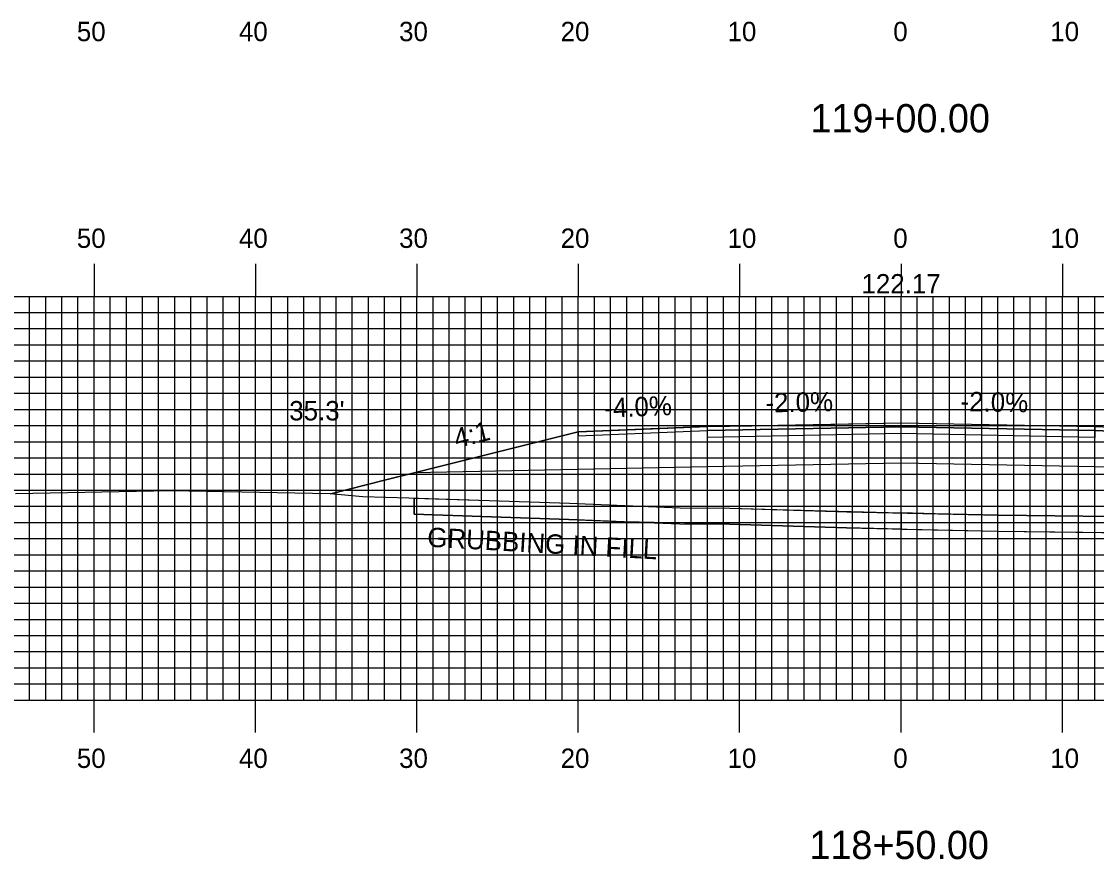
# Model space of a CAD drawing. Extents: x 1771629 to 1771972, y 442591 to 442811.
# Drawn here: x 1771740.1 to 1771806.7, y 442643.8 to 442695.7 of the extents above; entities that cross this region are included whole.
import ezdxf

# ---------------------------------------------------------------- set-up
doc = ezdxf.new("R2010")
doc.units = 0
for name, color, linetype in [('ANNOTATION', 7, 'Continuous'), ('D_Roadway_Centerline', 7, 'Continuous'), ('D_Roadway_Centerline_Text', 7, 'Continuous'), ('D_Roadway_Edge_Shoulder', 7, 'Continuous'), ('D_Roadway_Edge_TW', 7, 'Continuous'), ('D_Roadway_Pavement', 7, 'Continuous'), ('D_Roadway_SlopeLines', 7, 'Continuous'), ('D_Roadway_SubGrade', 7, 'Continuous'), ('D_Text_Standard', 7, 'Continuous'), ('GRUBBING IN FILL', 7, 'Continuous'), ('H_V ANNOTATION', 7, 'Continuous'), ('MAJOR', 7, 'Continuous'), ('MINOR', 7, 'Continuous'), ('S_Roadway_Centerline', 7, 'Continuous')]:
    doc.layers.add(name, color=color, linetype=linetype)

msp = doc.modelspace()

# ---------------------------------------------------------------- linework, layer by layer
at = {"layer": 'D_Roadway_Centerline'}
msp.add_lwpolyline([(1771759.249, 442666.447), (1771762.58, 442667.28), (1771764.404, 442667.736), (1771764.407, 442667.736), (1771764.42, 442667.74), (1771772.599, 442669.785), (1771774.581, 442670.28), (1771774.583, 442670.28), (1771778.655, 442670.443), (1771782.581, 442670.6), (1771782.585, 442670.6), (1771785.333, 442670.655), (1771794.58, 442670.84), (1771806.564, 442670.601), (1771806.581, 442670.6), (1771806.592, 442670.6), (1771814.581, 442670.28), (1771814.588, 442670.278), (1771822.681, 442668.255), (1771824.754, 442667.736), (1771824.757, 442667.736), (1771836.89, 442664.702)], dxfattribs=at)
at = {"layer": 'D_Roadway_Edge_Shoulder'}
for points in [[(1771782.581, 442670.6), (1771774.581, 442670.28), (1771774.581, 442670.03), (1771782.581, 442670.35)], [(1771806.581, 442670.6), (1771814.581, 442670.28), (1771814.581, 442670.03), (1771806.581, 442670.35)]]:
    msp.add_lwpolyline(points, close=True, dxfattribs=at)
at = {"layer": 'D_Roadway_Edge_TW'}
msp.add_lwpolyline([(1771782.581, 442670.35), (1771782.581, 442670.6), (1771794.58, 442670.84), (1771806.581, 442670.6), (1771806.581, 442670.35), (1771794.58, 442670.59)], close=True, dxfattribs=at)
at = {"layer": 'D_Roadway_Pavement'}
msp.add_lwpolyline([(1771782.581, 442669.933), (1771782.581, 442670.35), (1771794.58, 442670.59), (1771806.581, 442670.35), (1771806.581, 442669.933), (1771794.58, 442670.173)], close=True, dxfattribs=at)
at = {"layer": 'D_Roadway_SlopeLines'}
msp.add_lwpolyline([(1771774.581, 442670.28), (1771764.407, 442667.736), (1771762.58, 442667.28), (1771759.249, 442666.447)], dxfattribs=at)
at = {"layer": 'D_Roadway_SubGrade'}
msp.add_lwpolyline([(1771782.581, 442668.1), (1771764.407, 442667.736), (1771774.581, 442670.28), (1771774.581, 442670.03), (1771782.581, 442670.35), (1771794.58, 442670.59), (1771806.581, 442670.35), (1771814.581, 442670.03), (1771814.581, 442670.28), (1771824.754, 442667.736), (1771806.581, 442668.1), (1771794.58, 442668.34)], close=True, dxfattribs=at)
at = {"layer": 'GRUBBING IN FILL'}
msp.add_line((1771764.407, 442666.174), (1771764.407, 442665.173), dxfattribs=at)
msp.add_line((1771764.407, 442666.174), (1771764.407, 442665.173), dxfattribs=at)
for points in [[(1771764.407, 442666.174), (1771769.054, 442666.018), (1771774.033, 442665.85), (1771780.897, 442665.574), (1771783.979, 442665.55), (1771787.6, 442665.439), (1771794.58, 442665.253), (1771794.58, 442664.253), (1771791.195, 442664.327), (1771783.959, 442664.55), (1771777.434, 442664.713), (1771773.996, 442664.851), (1771769.201, 442665.012), (1771764.407, 442665.173)], [(1771764.407, 442666.174), (1771769.054, 442666.018), (1771774.033, 442665.85), (1771780.897, 442665.574), (1771783.979, 442665.55), (1771787.6, 442665.439), (1771794.58, 442665.253), (1771794.58, 442664.253), (1771791.195, 442664.327), (1771783.959, 442664.55), (1771777.434, 442664.713), (1771773.996, 442664.851), (1771769.201, 442665.012), (1771764.407, 442665.173)], [(1771824.754, 442664.79), (1771819.881, 442664.889), (1771815.873, 442664.937), (1771810.246, 442665.005), (1771805.849, 442665.057), (1771800.611, 442665.12), (1771796.705, 442665.206), (1771794.58, 442665.253), (1771794.58, 442664.253), (1771800.594, 442664.12), (1771810.232, 442664.005), (1771819.869, 442663.889), (1771824.754, 442663.79)], [(1771824.754, 442664.79), (1771819.881, 442664.889), (1771815.873, 442664.937), (1771810.246, 442665.005), (1771805.849, 442665.057), (1771800.611, 442665.12), (1771796.705, 442665.206), (1771794.58, 442665.253), (1771794.58, 442664.253), (1771800.594, 442664.12), (1771810.232, 442664.005), (1771819.869, 442663.889), (1771824.754, 442663.79)]]:
    msp.add_lwpolyline(points, close=True, dxfattribs=at)
msp.add_lwpolyline([(1771764.407, 442665.173), (1771773.996, 442664.851), (1771780.873, 442664.574), (1771783.959, 442664.55), (1771791.195, 442664.327), (1771800.594, 442664.12), (1771819.869, 442663.889), (1771820.358, 442663.884), (1771820.72, 442663.874), (1771824.754, 442663.79)], dxfattribs=at)
msp.add_lwpolyline([(1771764.407, 442665.173), (1771773.996, 442664.851), (1771780.873, 442664.574), (1771783.959, 442664.55), (1771791.195, 442664.327), (1771800.594, 442664.12), (1771819.869, 442663.889), (1771820.358, 442663.884), (1771820.72, 442663.874), (1771824.754, 442663.79)], dxfattribs=at)
at = {"layer": 'MAJOR'}
for p, q in [((1771744.58, 442680.669), (1771744.58, 442678.665)), ((1771754.58, 442680.669), (1771754.58, 442678.665)), ((1771764.58, 442680.669), (1771764.58, 442678.665)), ((1771774.58, 442680.669), (1771774.58, 442678.665)), ((1771784.58, 442680.669), (1771784.58, 442678.665)), ((1771794.58, 442680.669), (1771794.58, 442678.665)), ((1771804.58, 442680.669), (1771804.58, 442678.665)), ((1771654.58, 442678.665), (1771934.58, 442678.665)), ((1771654.58, 442678.665), (1771934.58, 442678.665)), ((1771744.58, 442653.665), (1771744.58, 442678.665)), ((1771754.58, 442653.665), (1771754.58, 442678.665)), ((1771764.58, 442653.665), (1771764.58, 442678.665)), ((1771774.58, 442653.665), (1771774.58, 442678.665)), ((1771784.58, 442653.665), (1771784.58, 442678.665)), ((1771794.58, 442653.665), (1771794.58, 442678.665)), ((1771804.58, 442653.665), (1771804.58, 442678.665)), ((1771654.58, 442673.665), (1771934.58, 442673.665)), ((1771654.58, 442668.665), (1771934.58, 442668.665)), ((1771654.58, 442663.665), (1771934.58, 442663.665)), ((1771654.58, 442658.665), (1771934.58, 442658.665)), ((1771654.58, 442653.665), (1771934.58, 442653.665)), ((1771654.58, 442653.665), (1771934.58, 442653.665)), ((1771744.58, 442651.661), (1771744.58, 442653.665)), ((1771754.58, 442651.661), (1771754.58, 442653.665)), ((1771764.58, 442651.661), (1771764.58, 442653.665)), ((1771774.58, 442651.661), (1771774.58, 442653.665)), ((1771784.58, 442651.661), (1771784.58, 442653.665)), ((1771794.58, 442651.661), (1771794.58, 442653.665)), ((1771804.58, 442651.661), (1771804.58, 442653.665))]:
    msp.add_line(p, q, dxfattribs=at)
at = {"layer": 'MINOR'}
for p, q in [((1771740.58, 442653.665), (1771740.58, 442678.665)), ((1771741.58, 442653.665), (1771741.58, 442678.665)), ((1771742.58, 442653.665), (1771742.58, 442678.665)), ((1771743.58, 442653.665), (1771743.58, 442678.665)), ((1771745.58, 442653.665), (1771745.58, 442678.665)), ((1771746.58, 442653.665), (1771746.58, 442678.665)), ((1771747.58, 442653.665), (1771747.58, 442678.665)), ((1771748.58, 442653.665), (1771748.58, 442678.665)), ((1771749.58, 442653.665), (1771749.58, 442678.665)), ((1771750.58, 442653.665), (1771750.58, 442678.665)), ((1771751.58, 442653.665), (1771751.58, 442678.665)), ((1771752.58, 442653.665), (1771752.58, 442678.665)), ((1771753.58, 442653.665), (1771753.58, 442678.665)), ((1771755.58, 442653.665), (1771755.58, 442678.665)), ((1771756.58, 442653.665), (1771756.58, 442678.665)), ((1771757.58, 442653.665), (1771757.58, 442678.665)), ((1771758.58, 442653.665), (1771758.58, 442678.665)), ((1771759.58, 442653.665), (1771759.58, 442678.665)), ((1771760.58, 442653.665), (1771760.58, 442678.665)), ((1771761.58, 442653.665), (1771761.58, 442678.665)), ((1771762.58, 442653.665), (1771762.58, 442678.665)), ((1771763.58, 442653.665), (1771763.58, 442678.665)), ((1771765.58, 442653.665), (1771765.58, 442678.665)), ((1771766.58, 442653.665), (1771766.58, 442678.665)), ((1771767.58, 442653.665), (1771767.58, 442678.665)), ((1771768.58, 442653.665), (1771768.58, 442678.665)), ((1771769.58, 442653.665), (1771769.58, 442678.665)), ((1771770.58, 442653.665), (1771770.58, 442678.665)), ((1771771.58, 442653.665), (1771771.58, 442678.665)), ((1771772.58, 442653.665), (1771772.58, 442678.665)), ((1771773.58, 442653.665), (1771773.58, 442678.665)), ((1771775.58, 442653.665), (1771775.58, 442678.665)), ((1771776.58, 442653.665), (1771776.58, 442678.665)), ((1771777.58, 442653.665), (1771777.58, 442678.665)), ((1771778.58, 442653.665), (1771778.58, 442678.665)), ((1771779.58, 442653.665), (1771779.58, 442678.665)), ((1771780.58, 442653.665), (1771780.58, 442678.665)), ((1771781.58, 442653.665), (1771781.58, 442678.665)), ((1771782.58, 442653.665), (1771782.58, 442678.665)), ((1771783.58, 442653.665), (1771783.58, 442678.665)), ((1771785.58, 442653.665), (1771785.58, 442678.665)), ((1771786.58, 442653.665), (1771786.58, 442678.665)), ((1771787.58, 442653.665), (1771787.58, 442678.665)), ((1771788.58, 442653.665), (1771788.58, 442678.665)), ((1771789.58, 442653.665), (1771789.58, 442678.665)), ((1771790.58, 442653.665), (1771790.58, 442678.665)), ((1771791.58, 442653.665), (1771791.58, 442678.665)), ((1771792.58, 442653.665), (1771792.58, 442678.665)), ((1771793.58, 442653.665), (1771793.58, 442678.665)), ((1771795.58, 442653.665), (1771795.58, 442678.665)), ((1771796.58, 442653.665), (1771796.58, 442678.665)), ((1771797.58, 442653.665), (1771797.58, 442678.665)), ((1771798.58, 442653.665), (1771798.58, 442678.665)), ((1771799.58, 442653.665), (1771799.58, 442678.665)), ((1771800.58, 442653.665), (1771800.58, 442678.665)), ((1771801.58, 442653.665), (1771801.58, 442678.665)), ((1771802.58, 442653.665), (1771802.58, 442678.665)), ((1771803.58, 442653.665), (1771803.58, 442678.665)), ((1771805.58, 442653.665), (1771805.58, 442678.665)), ((1771806.58, 442653.665), (1771806.58, 442678.665)), ((1771654.58, 442677.665), (1771934.58, 442677.665)), ((1771654.58, 442676.665), (1771934.58, 442676.665)), ((1771654.58, 442675.665), (1771934.58, 442675.665)), ((1771654.58, 442674.665), (1771934.58, 442674.665)), ((1771654.58, 442672.665), (1771934.58, 442672.665)), ((1771654.58, 442671.665), (1771934.58, 442671.665)), ((1771654.58, 442670.665), (1771934.58, 442670.665)), ((1771654.58, 442669.665), (1771934.58, 442669.665)), ((1771654.58, 442667.665), (1771934.58, 442667.665)), ((1771654.58, 442666.665), (1771934.58, 442666.665)), ((1771654.58, 442665.665), (1771934.58, 442665.665)), ((1771654.58, 442664.665), (1771934.58, 442664.665)), ((1771654.58, 442662.665), (1771934.58, 442662.665)), ((1771654.58, 442661.665), (1771934.58, 442661.665)), ((1771654.58, 442660.665), (1771934.58, 442660.665)), ((1771654.58, 442659.665), (1771934.58, 442659.665)), ((1771654.58, 442657.665), (1771934.58, 442657.665)), ((1771654.58, 442656.665), (1771934.58, 442656.665)), ((1771654.58, 442655.665), (1771934.58, 442655.665)), ((1771654.58, 442654.665), (1771934.58, 442654.665))]:
    msp.add_line(p, q, dxfattribs=at)
at = {"layer": 'S_Roadway_Centerline'}
msp.add_lwpolyline([(1771739.704, 442666.461), (1771749.349, 442666.644), (1771759.215, 442666.45), (1771761.237, 442666.272), (1771764.075, 442666.185), (1771774.033, 442665.85), (1771780.897, 442665.574), (1771783.979, 442665.55), (1771791.222, 442665.327), (1771800.611, 442665.12), (1771819.881, 442664.889), (1771820.378, 442664.884), (1771820.744, 442664.873), (1771832.005, 442664.639), (1771840.262, 442664.746), (1771847.726, 442664.622), (1771855.867, 442664.271)], dxfattribs=at)

# ---------------------------------------------------------------- texts
at = {"layer": 'ANNOTATION'}
for s, rotation, p in [('-4.0%', 2.29059, (1771776.214, 442671.147)), ('-2.0%', 1.14584, (1771786.189, 442671.473)), ('-2.0%', 358.85428, (1771798.258, 442671.567)), ('4:1', 14.03844, (1771767.045, 442669.258))]:
    msp.add_text(s, height=1.2, rotation=rotation, dxfattribs=at).set_placement(p)
at = {"layer": 'D_Roadway_Centerline'}
for s, p in [('C', (1771794.575, 442670.84)), ('L', (1771794.58, 442670.833))]:
    msp.add_text(s, height=0.0146, dxfattribs=at).set_placement(p)
at = {"layer": 'D_Roadway_Centerline_Text'}
msp.add_text('122.17', height=1.2, dxfattribs=at).set_placement((1771792.13, 442678.844))
at = {"layer": 'D_Text_Standard'}
msp.add_text("35.3'", height=1.2, dxfattribs=at).set_placement((1771756.671, 442670.984))
at = {"layer": 'GRUBBING IN FILL'}
msp.add_text('GRUBBING IN FILL', height=1.2, rotation=356.82289, dxfattribs=at).set_placement((1771765.2, 442663.168))
at = {"layer": 'H_V ANNOTATION'}
for s, height, p in [('50', 1.2, (1771743.51, 442694.465)), ('40', 1.2, (1771753.553, 442694.465)), ('30', 1.2, (1771763.478, 442694.465)), ('20', 1.2, (1771773.488, 442694.465)), ('10', 1.2, (1771783.831, 442694.465)), ('0', 1.2, (1771794.099, 442694.465)), ('10', 1.2, (1771803.831, 442694.465)), ('119+00.00', 1.75, (1771788.963, 442688.821)), ('50', 1.2, (1771743.51, 442681.665)), ('40', 1.2, (1771753.553, 442681.665)), ('30', 1.2, (1771763.478, 442681.665)), ('20', 1.2, (1771773.488, 442681.665)), ('10', 1.2, (1771783.831, 442681.665)), ('0', 1.2, (1771794.099, 442681.665)), ('10', 1.2, (1771803.831, 442681.665)), ('50', 1.2, (1771743.51, 442649.465)), ('40', 1.2, (1771753.553, 442649.465)), ('30', 1.2, (1771763.478, 442649.465)), ('20', 1.2, (1771773.488, 442649.465)), ('10', 1.2, (1771783.831, 442649.465)), ('0', 1.2, (1771794.099, 442649.465)), ('10', 1.2, (1771803.831, 442649.465)), ('118+50.00', 1.75, (1771788.9, 442643.821))]:
    msp.add_text(s, height=height, dxfattribs=at).set_placement(p)

doc.saveas('drawing.dxf')
